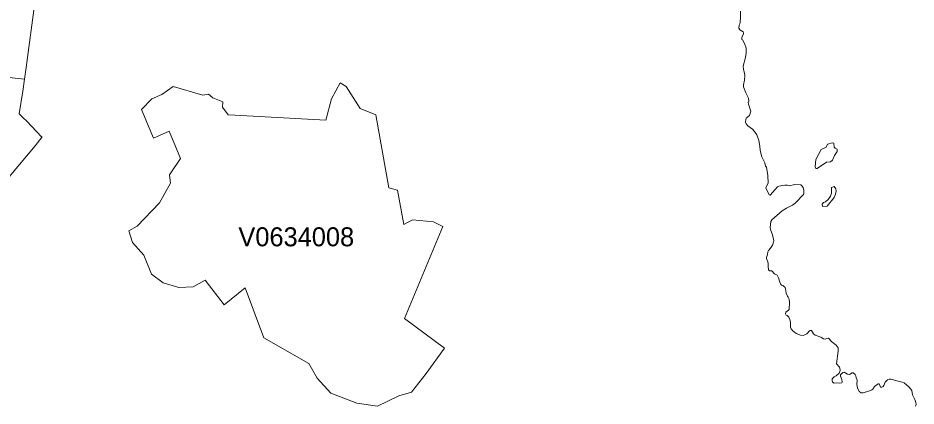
# Model space of a CAD drawing. Extents: x 369010 to 735936, y 6377141 to 6616555.
# Drawn here: x 445399 to 450130, y 6486690 to 6488735 of the extents above; entities that cross this region are included whole.
import ezdxf
from ezdxf.enums import TextEntityAlignment as Align

# ---------------------------------------------------------------- set-up
doc = ezdxf.new("R2010")
doc.units = 0
doc.header["$LTSCALE"] = 40
doc.layers.add('3', color=7, linetype='Continuous', lineweight=13)
doc.layers.add('4', color=7, linetype='Continuous')

msp = doc.modelspace()

# ---------------------------------------------------------------- linework, layer by layer
at = {"layer": '3'}
for points in [[(446862.13, 6489376.7), (446679.91, 6489535.25), (446445.72, 6489739.15), (446341.29, 6489647.13), (446240.99, 6489531.94), (446018.55, 6489317.28), (446002.67, 6489311.65), (445885.65, 6489328.53), (445860.5, 6489326.05), (445828.72, 6489306.69), (445786.52, 6489258.69), (445761.03, 6489203.74), (445742.16, 6489090.21), (445678.44, 6488985.11), (445582.12, 6488931.66), (445497.55, 6488889.29), (445489.27, 6488828.22), (445441.77, 6488475.03), (445433.17, 6488413.3)], [(445334.36, 6488422.73), (445433, 6488413.46), (445433.17, 6488413.3), (445441.77, 6488475.03), (445489.27, 6488828.22)], [(449348, 6487487.96), (449349.65, 6487503.36), (449352.8, 6487510.31), (449363.72, 6487522.55), (449373.98, 6487537.95), (449379.11, 6487553.34), (449380.11, 6487561.12), (449373.98, 6487591.9), (449364.71, 6487614.91), (449360.91, 6487630.3), (449364.38, 6487663.07), (449369.51, 6487670.52), (449424.96, 6487718.51), (449448.13, 6487733.57), (449478.58, 6487749.3), (449492.32, 6487759.89), (449536.34, 6487805.24), (449538.66, 6487810.04), (449539.49, 6487825.43), (449536.01, 6487840.82), (449528.89, 6487851.08), (449522.61, 6487855.55), (449491.82, 6487856.87), (449460.87, 6487850.75), (449453.26, 6487853.23), (449437.87, 6487853.56), (449407.08, 6487849.43), (449400.63, 6487845.62), (449361.57, 6487801.26), (449355.45, 6487803.25), (449338.4, 6487839.99), (449341.54, 6487849.43), (449351.14, 6487865.15), (449348.66, 6487905.53), (449342.37, 6487948.56), (449337.08, 6487953.36), (449332.61, 6487971.73), (449317.21, 6488002.52), (449308.61, 6488037.11), (449307.28, 6488060.28), (449301.82, 6488089.08), (449291.56, 6488118.7), (449278.98, 6488137.57), (449269.05, 6488149.15), (449243.4, 6488166.03), (449235.12, 6488176.96), (449231.81, 6488186.89), (449233.47, 6488200.79), (449235.79, 6488206.25), (449251.84, 6488221.97), (449259.45, 6488244.32), (449246.71, 6488281.56), (449245.72, 6488291.49), (449247.21, 6488292.15), (449248.53, 6488296.12), (449247.21, 6488313), (449233.14, 6488339.98), (449220.89, 6488372.09), (449221.22, 6488383.67), (449226.02, 6488406.68), (449228.01, 6488431.17), (449226.35, 6488443.92), (449220.39, 6488463.11), (449219.4, 6488481.15), (449231.81, 6488526.01), (449235.79, 6488551.66), (449235.46, 6488575.49), (449226.68, 6488600.15), (449214.93, 6488619.35), (449211.95, 6488622), (449212.62, 6488633.91), (449218.74, 6488646.66), (449220.89, 6488655.93), (449219.73, 6488662.05), (449201.36, 6488671.98), (449195.9, 6488681.74), (449197.39, 6488698.13), (449201.53, 6488703.59), (449203.68, 6488710.54), (449202.69, 6488720.8), (449204.67, 6488728.75), (449205, 6488771.78)], [(445352.07, 6487898.08), (445489.44, 6488061.93), (445525.52, 6488108.6), (445522.37, 6488107.94), (445445.91, 6488191.36), (445426.88, 6488209.56), (445404.7, 6488229.92), (445424.56, 6488350.24), (445433.17, 6488413.3), (445433, 6488413.46), (445334.36, 6488422.73)], [(445433.17, 6488413.3), (445424.56, 6488350.24), (445404.7, 6488229.92), (445426.88, 6488209.56), (445445.91, 6488191.36), (445522.37, 6488107.94), (445525.52, 6488108.6), (445489.44, 6488061.93), (445352.07, 6487898.08)], [(449960.86, 6486797.81), (449957.22, 6486793.34), (449949.94, 6486789.7), (449943.48, 6486790.03), (449935.37, 6486806.09), (449929.58, 6486806.75), (449910.71, 6486793.34), (449901.77, 6486779.44), (449896.64, 6486775.3), (449875.46, 6486766.04), (449862.55, 6486763.72), (449850.47, 6486758.59), (449840.87, 6486759.25), (449829.61, 6486767.36), (449821.51, 6486785.23), (449817.37, 6486802.61), (449819.68, 6486825.78), (449814.22, 6486837.86), (449812.9, 6486849.12), (449809.09, 6486855.9), (449799.16, 6486865.17), (449793.04, 6486864.51), (449778.64, 6486856.24), (449768.05, 6486857.56), (449751.66, 6486867.82), (449743.88, 6486865.84), (449732.3, 6486854.58), (449731.97, 6486846.97), (449739.08, 6486829.59), (449740.41, 6486815.69), (449739.42, 6486812.87), (449728.49, 6486810.72), (449710.62, 6486812.87), (449699.03, 6486810.06), (449689.93, 6486816.35), (449688.11, 6486823.8), (449688.44, 6486832.73), (449699.03, 6486843), (449709.62, 6486848.46), (449725.35, 6486863.19), (449730.48, 6486877.75), (449729.15, 6486889.17), (449726.01, 6486894.96), (449710.62, 6486912.01), (449720.22, 6486978.38), (449719.55, 6486996.42), (449709.29, 6487009.82), (449685.79, 6487028.86), (449668.91, 6487048.39), (449659.81, 6487046.4), (449651.2, 6487041.93), (449643.09, 6487043.26), (449633.82, 6487048.72), (449628.53, 6487053.52), (449597.91, 6487063.45), (449588.97, 6487070.89), (449578.38, 6487087.78), (449571.93, 6487087.78), (449567.79, 6487085.62), (449554.38, 6487070.23), (449544.29, 6487064.44), (449534.69, 6487061.46), (449521.28, 6487062.78), (449498.11, 6487073.05), (449481.23, 6487086.78), (449472.79, 6487096.55), (449468.98, 6487105.82), (449468.49, 6487130.48), (449465.18, 6487146.36), (449460.38, 6487157.45), (449451.27, 6487166.72), (449445.81, 6487169.37), (449443, 6487175.33), (449443.66, 6487185.09), (449450.11, 6487190.55), (449458.72, 6487194.36), (449461.2, 6487199.16), (449462.86, 6487237.72), (449460.87, 6487253.11), (449456.07, 6487263.38), (449451.93, 6487268.51), (449446.14, 6487283.9), (449444.32, 6487299.29), (449440.02, 6487314.02), (449428.6, 6487324.61), (449421.81, 6487327.09), (449415.03, 6487334.54), (449411.55, 6487342.32), (449405.43, 6487365.33), (449398.97, 6487379.06), (449384.91, 6487386.18), (449370.51, 6487403.23), (449358.26, 6487402.23), (449353.46, 6487407.36), (449350.65, 6487426.23), (449351.14, 6487441.62), (449349.65, 6487449.4), (449341.54, 6487467.94), (449341.54, 6487472.41), (449348, 6487487.96)], [(450127.03, 6486689.41), (450129.84, 6486697.35), (450129.18, 6486708.94), (450124.05, 6486724.33), (450110.97, 6486748.66), (450106.83, 6486772.49), (450093.92, 6486790.03), (450066.95, 6486811.55), (450059, 6486815.19), (450041.63, 6486818.34), (449998.59, 6486831.41), (449988.33, 6486830.91), (449980.06, 6486827.27), (449966.82, 6486816.02), (449960.86, 6486797.81)]]:
    msp.add_lwpolyline(points, dxfattribs=at)
for points in [[(446540.39, 6488223.3), (446505.47, 6488224.62), (446475.68, 6488264.67), (446478.16, 6488293.31), (446425.2, 6488314), (446403.19, 6488333.36), (446373.39, 6488328.23), (446216.99, 6488373.41), (446156.09, 6488331.54), (446104.29, 6488309.53), (446048.68, 6488252.59), (446113.39, 6488102.48), (446194.82, 6488138.73), (446254.23, 6487994.74), (446197.3, 6487908.01), (446202.43, 6487865.31), (446144.34, 6487760.55), (446026.5, 6487638.74), (445983.3, 6487613.25), (446001.51, 6487552.35), (446062.25, 6487485.15), (446102.3, 6487385.35), (446163.2, 6487338.85), (446245.96, 6487314.19), (446320.93, 6487318.16), (446385.64, 6487353.08), (446485.28, 6487223.65), (446596.49, 6487312.53), (446694.8, 6487049.88), (446930.48, 6486914.82), (446975.83, 6486837.2), (447046.83, 6486756.93), (447184.03, 6486704.14), (447292.77, 6486689.9), (447405.31, 6486743.03), (447472.51, 6486763.72), (447548.8, 6486860.87), (447645.29, 6486994.1), (447435.43, 6487151.66), (447637.51, 6487635.43), (447588.36, 6487660.09), (447477.14, 6487671.67), (447431.79, 6487645.86), (447398.2, 6487826.92), (447353.01, 6487839.99), (447283.83, 6488224.46), (447201.08, 6488258.05), (447128.59, 6488373.25), (447096.15, 6488392.77), (447049.64, 6488309.86), (447019.85, 6488195.99)], [(446540.39, 6488223.3), (447019.85, 6488195.99), (447049.64, 6488309.86), (447096.15, 6488392.77), (447128.59, 6488373.25), (447201.08, 6488258.05), (447283.83, 6488224.46), (447353.01, 6487839.99), (447398.2, 6487826.92), (447431.79, 6487645.86), (447477.14, 6487671.67), (447588.36, 6487660.09), (447637.51, 6487635.43), (447435.43, 6487151.66), (447645.29, 6486994.1), (447548.8, 6486860.87), (447472.51, 6486763.72), (447405.31, 6486743.03), (447292.77, 6486689.9), (447184.03, 6486704.14), (447046.83, 6486756.93), (446975.83, 6486837.2), (446930.48, 6486914.82), (446694.8, 6487049.88), (446596.49, 6487312.53), (446485.28, 6487223.65), (446385.64, 6487353.08), (446320.93, 6487318.16), (446245.96, 6487314.19), (446163.2, 6487338.85), (446102.3, 6487385.35), (446062.25, 6487485.15), (446001.51, 6487552.35), (445983.3, 6487613.25), (446026.5, 6487638.74), (446144.34, 6487760.55), (446202.43, 6487865.31), (446197.3, 6487908.01), (446254.23, 6487994.74), (446194.82, 6488138.73), (446113.39, 6488102.48), (446048.68, 6488252.59), (446104.29, 6488309.53), (446156.09, 6488331.54), (446216.99, 6488373.41), (446373.39, 6488328.23), (446403.19, 6488333.36), (446425.2, 6488314), (446478.16, 6488293.31), (446475.68, 6488264.67), (446505.47, 6488224.62)], [(449689.93, 6488076.66), (449663.12, 6488069.21), (449656.99, 6488053.49), (449630.02, 6488041.58), (449601.72, 6487988.45), (449598.9, 6487950.55), (449602.05, 6487941.94), (449609.49, 6487941.94), (449657.33, 6487975.54), (449679.34, 6487977.19), (449689.93, 6487985.14), (449700.52, 6488010.46), (449713.76, 6488030.65), (449714.09, 6488043.56), (449703.17, 6488048.36), (449699.36, 6488053.49), (449697.05, 6488075.34)], [(449698.37, 6487846.28), (449684.63, 6487842.14), (449683.97, 6487811.86), (449679.67, 6487796.8), (449666.76, 6487777.6), (449652.86, 6487766.18), (449641.93, 6487761.87), (449634.49, 6487753.93), (449636.47, 6487742.34), (449662.12, 6487744.16), (449698.7, 6487788.85), (449706.31, 6487806.23), (449708.3, 6487823.44), (449706.65, 6487835.03)]]:
    msp.add_lwpolyline(points, close=True, dxfattribs=at)

# ---------------------------------------------------------------- texts
at = {"layer": '4'}
msp.add_text('V0634008', height=100, dxfattribs=at).set_placement((446864.88, 6487531.83), align=Align.CENTER)

doc.saveas('drawing.dxf')
